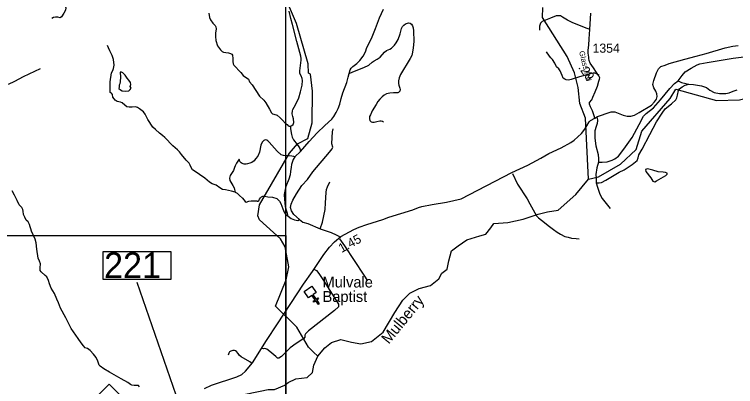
# Model space of a CAD drawing. Extents: x 1159738 to 1321356, y 736314 to 882035.
# Drawn here: x 1209848 to 1219753, y 803906 to 809013 of the extents above; entities that cross this region are included whole.
import ezdxf

# ---------------------------------------------------------------- set-up
doc = ezdxf.new("R2010")
doc.units = 0
for name, color, linetype in [('Exist Cultural Church CELL', 7, 'Continuous'), ('Exist Cultural Church Label', 7, 'Continuous'), ('Exist Hydrographic Creek Single Shore', 7, 'Continuous'), ('Exist Hydrographic Creek Single Shore Label', 7, 'Continuous'), ('Exist Hydrographic Pond Under 1500 Sq Ft', 7, 'Continuous'), ('Exist Road Non-System Type 51', 7, 'Continuous'), ('Exist Road Primary NC Attributed', 7, 'Continuous'), ('Exist Road Primary NC Mileage Hundredths English Label', 7, 'Continuous'), ('Exist Road Primary NC Shield CELL', 7, 'Continuous'), ('Exist Road Secondary Mileage Hundredths English Label', 7, 'Continuous'), ('Exist Road Secondary Structure Standard Bridge Number Label', 7, 'Continuous'), ('Exist Road Secondary Type 51 Attributed', 7, 'Continuous'), ('Exist Road Secondary Type 51 Label', 7, 'Continuous'), ('Exist Road Secondary Type 51 Number Label', 7, 'Continuous'), ('Map Preparation Inset Cut Line', 7, 'Continuous')]:
    doc.layers.add(name, color=color, linetype=linetype)

msp = doc.modelspace()

# ---------------------------------------------------------------- linework, layer by layer
at = {"layer": 'Exist Cultural Church CELL'}
msp.add_lwpolyline([(1213993.7, 805198.8), (1213947.4, 805165.7), (1213991.5, 805103.7), (1214017.6, 805122.2), (1214026.8, 805109.2), (1214000.8, 805090.7), (1214035.6, 805041.7), (1214022.6, 805032.4), (1213987.7, 805081.4), (1213961.6, 805062.8), (1213952.4, 805075.9), (1213978.4, 805094.4), (1213934.3, 805156.4), (1213887.3, 805123.1), (1213825.5, 805209.8), (1213932, 805285.6)], close=True, dxfattribs=at)
at = {"layer": 'Exist Hydrographic Creek Single Shore'}
for points in [[(1214013.3, 804322.9), (1213956.3, 804378.4), (1213886.3, 804446.5), (1213727.3, 804718.8), (1213435.3, 805010.2), (1213578.3, 805371.7), (1213616.3, 805548.2), (1213565.3, 805825), (1213501.3, 805934.6), (1213216.3, 806193.1), (1213193.3, 806249.3), (1213214.2, 806399.9), (1213625.3, 807107.3), (1213737.2, 807236.4), (1213880.2, 807309), (1213936.2, 807524.5), (1213940.2, 807957.8), (1213913.3, 808191.3), (1213888.2, 808208.3), (1213883.2, 808333.1), (1213723.2, 808887.8), (1213597.2, 809175.9)], [(1217735.3, 806752.5), (1217690.3, 807587.2), (1217613.3, 807788.9), (1217593.3, 808009.3), (1217541.2, 808210.5), (1217438.3, 808435.9), (1217103.2, 808971.1), (1217106.8, 809110.1)], [(1217735.3, 806752.5), (1217869.3, 806782.7), (1218174.3, 806957.1), (1218388.3, 807159.6), (1218467.2, 807409.5), (1218856.6, 807857.7), (1218930.6, 807986.3), (1219490.3, 807830.1), (1219807.3, 807840.2), (1220345.3, 807973.8)], [(1214013.3, 804322.9), (1214112, 804437.9), (1214204.7, 804510.6), (1214329.7, 804551), (1214479, 804514.6), (1214608, 804490.4), (1214753.2, 804522.7), (1214910.5, 804651.8), (1215071.8, 804922.3), (1215180.7, 805091.8), (1215277.5, 805188.6), (1215406.6, 805253.2), (1215563.9, 805293.6), (1215676.8, 805382.3), (1215717.1, 805463.1), (1215789.7, 805515.5), (1215813.9, 805632.6), (1215850.2, 805769.8), (1215943, 805838.4), (1216064, 805919.1), (1216241.4, 805975.6), (1216321.1, 805997.8), (1216393.7, 806082.6), (1216434, 806143.1), (1216623.6, 806155.2), (1216837.3, 806203.7), (1217043, 806272.3), (1217172.1, 806304.6), (1217317.3, 806324.7), (1217559.3, 806542.7), (1217735.3, 806752.5)], [(1212212.4, 803125.7), (1212271, 803160.6), (1212404, 803221.1), (1212525, 803285.7), (1212585.5, 803342.2), (1212623.3, 803452.6), (1212601.7, 803535.9), (1212601.7, 803576.3), (1212654.1, 803661), (1212738.8, 803725.6), (1212976.8, 803790.2), (1213222.8, 803842.6), (1213331.7, 803866.9), (1213420.4, 803866.9), (1213561.6, 803923.4), (1213605.9, 803959.7), (1213714.8, 804012.2), (1213868.1, 804032.3), (1213940.7, 804100.9), (1213960.8, 804197.8), (1214013.3, 804322.9)]]:
    msp.add_lwpolyline(points, dxfattribs=at)
at = {"layer": 'Exist Hydrographic Pond Under 1500 Sq Ft'}
for points in [[(1211301.1, 808219.1), (1211305.5, 808151.9), (1211301.1, 808094.6), (1211294.5, 808059.3), (1211287.9, 808043.9), (1211284.6, 808018.6), (1211283.5, 807997.6), (1211305.5, 807977.8), (1211326.4, 807962.4), (1211378.1, 807958), (1211417.8, 807962.4), (1211438.7, 807982.2), (1211450.8, 807999.8), (1211439.8, 808023), (1211446.4, 808052.7), (1211440.9, 808080.3), (1211418.9, 808108.9), (1211395.8, 808138.7), (1211368.2, 808178.3), (1211337.4, 808210.3), (1211319.8, 808222.4)], [(1218517.9, 806884.6), (1218521.4, 806859.1), (1218587.4, 806772.1), (1218618.7, 806724.6), (1218641.9, 806717.6), (1218668.5, 806731.5), (1218793.7, 806801.1), (1218812.2, 806822), (1218814.5, 806834.8), (1218791.4, 806845.2), (1218757.8, 806846.3), (1218689.4, 806854.5), (1218615.2, 806874.2), (1218560.8, 806888.1), (1218541.1, 806892.7), (1218529.5, 806891.6)]]:
    msp.add_lwpolyline(points, close=True, dxfattribs=at)
at = {"layer": 'Exist Road Non-System Type 51'}
msp.add_line((1213777.1, 807132.2), (1213698.1, 807059), dxfattribs=at)
for points in [[(1210456.7, 809178.8), (1210516.3, 809145.9), (1210538.9, 809129.4), (1210549.2, 809116), (1210552.3, 809101.6), (1210548.2, 809072.8), (1210526.6, 809029.6), (1210496.8, 808982.2), (1210478.3, 808967.8), (1210444.3, 808974), (1210411.4, 808974), (1210384.7, 808969.9), (1210361, 808956.5)], [(1213638.4, 807481.5), (1213657.9, 807488.7), (1213678.5, 807504.2), (1213686.7, 807528.9), (1213682.6, 807578.3), (1213671.3, 807613.3), (1213662.1, 807647.2), (1213666.2, 807688.4), (1213671.3, 807706.9), (1213688.8, 807739.9), (1213726.8, 807807.8), (1213752.2, 807869.7), (1213775.9, 807952.1), (1213798.5, 808041.6), (1213804.6, 808104.4), (1213799.5, 808135.3), (1213785.1, 808168.2), (1213769.7, 808202.1), (1213767.6, 808240.2), (1213776.9, 808311.2), (1213786.1, 808385.3), (1213788.2, 808408.4), (1213783.1, 808441.3), (1213726.5, 808643), (1213669, 808875.1), (1213644.4, 808957.9), (1213622.8, 809055.7)], [(1214445.8, 808201.7), (1214458.1, 808252.1), (1214471.5, 808274.8), (1214498.2, 808300.5), (1214551.7, 808340.6), (1214591.8, 808379.7), (1214638.1, 808441.5), (1214672, 808501.2), (1214690.5, 808557.8), (1214752, 808681.4), (1214808.6, 808818.3), (1214864.1, 808965.5), (1214918.6, 809083.8)], [(1212517.2, 809029.1), (1212529.5, 808970.5), (1212541.9, 808937.5), (1212572.7, 808895.3), (1212603.6, 808863.4), (1212612.8, 808842.3), (1212616.9, 808813.5), (1212611.8, 808753.8), (1212609.7, 808710.6), (1212613.8, 808654), (1212639.5, 808579.9), (1212678.6, 808525.3), (1212701.2, 808503.7), (1212721.8, 808493.4), (1212753.7, 808489.3), (1212790.7, 808486.2), (1212816.2, 808478.6), (1212832.6, 808467.3), (1212842.9, 808455), (1212849.1, 808408.6), (1212847, 808367.5), (1212852.2, 808336.6), (1212860.4, 808316), (1212956, 808217.2), (1212990, 808175), (1213062, 808125.6), (1213078.4, 808089.6), (1213115.4, 808048.4), (1213215.9, 807889.6), (1213272.5, 807837.2), (1213299.2, 807799.1), (1213349.6, 807711.6), (1213378.4, 807664.3), (1213392.6, 807650.3), (1213409.1, 807644.1), (1213457.4, 807628.7), (1213499.6, 807591.7), (1213531.4, 807561.8), (1213573.6, 807515.5), (1213592.1, 807502.1), (1213608.6, 807485.7), (1213621.9, 807481.5), (1213638.4, 807481.5)], [(1217757.8, 808805.5), (1217716.5, 808822.1), (1217610.4, 808860.7), (1217508.5, 808902), (1217445.1, 808932.3), (1217374.9, 808977.8), (1217348.7, 808993), (1217321.1, 808995.7), (1217286.7, 808991.6), (1217210.9, 808959.9), (1217098, 808914.4), (1217075.9, 808891), (1217060.8, 808852.4), (1217062.2, 808827.6), (1217060.8, 808795.9)], [(1214445.8, 808201.7), (1214496.6, 808223.2), (1214645.8, 808283.9), (1214714.1, 808315.7), (1214762.3, 808356.2), (1214786.9, 808377.1), (1214828.3, 808400.2), (1214870.7, 808426.2), (1214933.3, 808494.6), (1214960.2, 808517.7), (1215006.4, 808538), (1215029.5, 808549.5), (1215068, 808592.9), (1215090.2, 808621.8), (1215118, 808670.4), (1215144.9, 808746.6), (1215164.2, 808818.8), (1215179.6, 808848.7), (1215195, 808867), (1215220, 808886.3), (1215262.4, 808896.9), (1215284.3, 808893.9), (1215301.6, 808881.4), (1215317, 808858.2), (1215326.7, 808828.4), (1215331.5, 808787), (1215332.4, 808642.4), (1215323.8, 808555.7), (1215316.1, 808494.1), (1215304.5, 808447.8), (1215283.3, 808408.3), (1215149.7, 808190.2), (1215131.4, 808144), (1215122.7, 808102.6), (1215122.7, 808066), (1215128.5, 808042.8), (1215141, 808000.9), (1215146.8, 807983.6), (1215141, 807961.4), (1215133.3, 807948.9), (1215123.7, 807943.1), (1215114.1, 807938.3), (1215054.4, 807935.4), (1215005.3, 807932.5), (1214957.1, 807921.9), (1214925.4, 807906.5), (1214901.3, 807883.4), (1214868.6, 807848.7), (1214840.6, 807818.8), (1214815.6, 807778.4), (1214761.9, 807692.2), (1214751.3, 807668.1), (1214738.8, 807636.3), (1214727.3, 807611.3), (1214725.4, 807580.4), (1214730.2, 807555.4), (1214746.5, 807539), (1214766.8, 807533.2), (1214787.9, 807534.2), (1214826.4, 807542.9), (1214866.9, 807552.5), (1214884.2, 807553.4), (1214902.5, 807548.6), (1214916.8, 807539.6)], [(1212878.6, 806572.1), (1212829.1, 806586.5), (1212748.7, 806605.2), (1212704.7, 806611.8), (1212667.2, 806631.6), (1212619.9, 806668), (1212565.9, 806687.8), (1212526.3, 806711), (1212461.3, 806764.9), (1212392, 806815.6), (1212315.4, 806865.9), (1212293.3, 806882.4), (1212275.7, 806913.3), (1212263.6, 806944.1), (1212249.3, 806973.9), (1212206.4, 807012.4), (1212141.4, 807089.5), (1212115, 807127), (1212088.5, 807156.8), (1212025.8, 807209.6), (1211913.7, 807322.5), (1211881.8, 807351.2), (1211839.9, 807385.3), (1211783.8, 807431.6), (1211750.7, 807468), (1211680.3, 807571.5), (1211657.5, 807617.3), (1211645.4, 807644.8), (1211618.9, 807676.8), (1211567.2, 807716.2), (1211539.7, 807737.2), (1211513.3, 807743.8), (1211467, 807741.6), (1211425.2, 807738.3), (1211394.3, 807746), (1211362.4, 807769.1), (1211326.1, 807797.8), (1211304.1, 807807.7), (1211257.8, 807819.8), (1211232.5, 807835.2), (1211216, 807852.9), (1211198.4, 807877.1), (1211194, 807914.6), (1211179.6, 807933.3), (1211161.7, 807942.7), (1211162.8, 807968.1), (1211163.9, 808088.2), (1211180.4, 808209.4), (1211199.1, 808243.5), (1211209, 808270), (1211217.8, 808315.1), (1211209.9, 808392.7), (1211191.1, 808448.9), (1211160.3, 808515), (1211139.6, 808555.3), (1211127.5, 808585)], [(1217879, 808180.4), (1217843.2, 808198.3), (1217819.8, 808205.2), (1217797.7, 808208), (1217771.6, 808203.8), (1217593.9, 808152.8), (1217494.7, 808119.7), (1217457.5, 808108.7), (1217427.2, 808114.2), (1217407.9, 808123.9), (1217384.5, 808137.7), (1217369.3, 808174.9), (1217344.6, 808241), (1217323.9, 808268.6), (1217295, 808293.4), (1217271.5, 808345.8), (1217239.9, 808395.4), (1217216.4, 808417.5), (1217195.8, 808438.2), (1217157.2, 808498.8)], [(1218963.8, 808102.9), (1219017.5, 808176), (1219058.8, 808224.2), (1219141.5, 808276.6), (1219224.1, 808319.3), (1219264.1, 808335.9), (1219361.9, 808355.2), (1219720.8, 808412.7), (1219970.2, 808445.8), (1220177.7, 808462.2), (1220227.3, 808463.6), (1220250.2, 808460.9)], [(1209768.8, 808055.7), (1209854.1, 808095.8), (1209972.4, 808160.2), (1210205.1, 808271.5)], [(1213777.1, 807132.2), (1213894.5, 807268), (1214006.2, 807387.5), (1214113.1, 807486.7), (1214208.9, 807576.6), (1214234.9, 807611.3), (1214267.6, 807666.2), (1214294.6, 807724), (1214318.6, 807779.9), (1214335, 807859.9), (1214360, 807936.9), (1214411.8, 808079.7), (1214431.1, 808151), (1214445.8, 808201.7)], [(1217869.1, 806984.9), (1217921.7, 806986.7), (1217989.2, 806992.2), (1218056.7, 807011.5), (1218095.2, 807030.8), (1218144.8, 807068), (1218220.6, 807163.1), (1218330.8, 807325.8), (1218427.2, 807503.6), (1218490.3, 807618.6), (1218523.3, 807651.6), (1218625.3, 807733), (1218723.1, 807840.5), (1218848.4, 807994.9), (1218914.2, 808064.3), (1218963.8, 808102.9)], [(1218963.8, 808102.9), (1219010.6, 808079.5), (1219068.4, 808065.7), (1219110.8, 808055.3)], [(1217836.1, 806703), (1217878.6, 806700.5), (1217913, 806704.7), (1217969.5, 806736.4), (1218154.1, 806846.6), (1218221.6, 806878.3), (1218334.5, 806951.4), (1218399.3, 807009.3), (1218415.8, 807045.1), (1218425.4, 807087.9), (1218468.1, 807163.7), (1218573.9, 807365.3), (1218668.9, 807540.4), (1218746.1, 807656.2), (1218786, 807716.8), (1218871.4, 807787.1), (1218930.4, 807841.7), (1218944.1, 807867.8), (1218953.8, 807905.1), (1218967.6, 807968.5), (1218981.3, 807991.9), (1219019.9, 808019.5), (1219061.2, 808042.9), (1219110.8, 808055.3), (1219176.9, 808049.8), (1219287.1, 808033.3), (1219351.9, 808011.2), (1219401.5, 807975.4), (1219460, 807943.7), (1219531.7, 807928.5), (1219621.2, 807925.8), (1219665.3, 807935.4), (1219720.4, 807958.9), (1219774.1, 807978.2)], [(1217849.8, 807594.2), (1217858.1, 807557), (1217852.6, 807517), (1217840.2, 807472.9), (1217822.3, 807416.4), (1217818.2, 807366.8), (1217818.2, 807314.4), (1217834.7, 807211), (1217865, 807089.7), (1217871.9, 807029), (1217869.1, 806984.9)], [(1213638.4, 807481.5), (1213639.4, 807444.3), (1213653.8, 807366.3), (1213662.5, 807328.7), (1213680.8, 807293.1), (1213733.7, 807227.6), (1213754, 807195.8), (1213768.4, 807172.7), (1213773.2, 807150.5), (1213777.1, 807132.2)], [(1213762.6, 806199.4), (1213683.8, 806265.8), (1213655.1, 806316), (1213640.7, 806362.7), (1213649.7, 806407.5), (1213673, 806464.9), (1213723.2, 806549.2), (1213794.9, 806665.8), (1213873.8, 806746.6), (1213947.3, 806852.4), (1214174.4, 807122.5), (1214213.8, 807167.3), (1214221, 807190.7), (1214208.4, 807239.1), (1214210.2, 807323.4), (1214215.6, 807402.3), (1214224.6, 807441.8)], [(1213698.1, 807059), (1213683.9, 807063.8), (1213658.6, 807069.3), (1213621.2, 807071.5), (1213589.2, 807071.5), (1213545.2, 807074.8), (1213513.3, 807088), (1213457.1, 807138.7), (1213345.9, 807258.8), (1213329.4, 807278.6), (1213314, 807286.4), (1213289.8, 807290.8), (1213272.1, 807284.2), (1213249, 807262.1), (1213233.6, 807216.9), (1213216, 807124.4), (1213189.6, 807068.2), (1213159.8, 807030.7), (1213138.9, 807004.3), (1213108.1, 806982.3), (1213082.8, 806970.1), (1213050.8, 806962.4), (1213028.8, 806958), (1213004.6, 806956.9), (1212974.9, 806967.9), (1212960.6, 806977.9), (1212946.2, 806996.6), (1212936.3, 807026.3)], [(1212936.3, 807026.3), (1212898.4, 806972.7), (1212880.8, 806936.3), (1212868.7, 806911), (1212855.5, 806869.1), (1212812.6, 806804.1), (1212802.6, 806764.5), (1212808.2, 806735.8), (1212850, 806666.4), (1212864.3, 806632.7), (1212870.9, 806611.8), (1212878.6, 806572.1)], [(1213698.1, 807059), (1213678, 807020.8), (1213654.7, 806954.4), (1213647.6, 806918.5), (1213642.2, 806855.7), (1213635, 806810.9), (1213618.9, 806753.5), (1213577.6, 806651.2), (1213565.1, 806608.2), (1213552.5, 806541.8), (1213556.1, 806473.6), (1213561.5, 806425.2), (1213565.1, 806376.8), (1213581.2, 806326.5), (1213593.8, 806283.5), (1213600.9, 806253), (1213606.3, 806245.8)], [(1217869.1, 806984.9), (1217847.1, 806909.8), (1217833.3, 806816.1), (1217836.1, 806765.1), (1217836.1, 806703)], [(1216687, 806830.4), (1216760, 806685.5), (1216889.8, 806480.2), (1216929.1, 806415.9), (1217020.6, 806251.2), (1217045, 806221.1), (1217085.5, 806187.4), (1217196.8, 806103.9), (1217253.1, 806060.5), (1217301.8, 806023.4), (1217350.4, 805996.8), (1217408.4, 805966.6), (1217452.4, 805955), (1217499.9, 805944.6), (1217563.6, 805939.9), (1217603, 805933)], [(1214045.9, 806072.1), (1214077.5, 806162.3), (1214117, 806334.5), (1214122.3, 806427.8), (1214127.7, 806571.3), (1214134.9, 806612.6), (1214149.2, 806646.6), (1214179.7, 806716.6)], [(1217836.1, 806703), (1217856.8, 806641), (1217888.4, 806545.9), (1217918.6, 806486.1), (1218032.9, 806349.6)], [(1209989, 806230), (1209973.9, 806265.8), (1209970.4, 806311.1), (1209961.7, 806337.2), (1209947.8, 806363.3), (1209930.4, 806382.5), (1209914.7, 806401.7), (1209886.9, 806459.1), (1209848.6, 806534), (1209817.2, 806589.8)], [(1212878.6, 806572.1), (1212909.3, 806558.2), (1212939.8, 806527.7), (1212981, 806490), (1213016.9, 806443.4), (1213033, 806434.4), (1213067.1, 806448.8), (1213097.6, 806454.2), (1213137, 806456), (1213176.4, 806456), (1213183.6, 806452.4), (1213196.2, 806450.6), (1213205.1, 806456), (1213215.9, 806477.5), (1213226.6, 806497.2), (1213242.8, 806509.8), (1213258.9, 806518.7), (1213287.6, 806518.7), (1213327, 806511.6), (1213391.6, 806504.4), (1213452.5, 806486.4), (1213490.2, 806450.6), (1213508.1, 806420.1), (1213535, 806342.9), (1213551.1, 806299.9), (1213570.8, 806271.2), (1213592.3, 806255), (1213606.3, 806245.8)], [(1211567.8, 803902.3), (1211552.1, 803919.4), (1211535, 803922.3), (1211513.6, 803922.3), (1211490.7, 803922.3), (1211460.7, 803923.7), (1211442.1, 803932.3), (1211403.5, 803960.9), (1211315, 804010.9), (1211249.2, 804048.1), (1211154.9, 804105.3), (1211076.3, 804151), (1211026.3, 804183.9), (1211013.5, 804201.1), (1210993.5, 804255.4), (1210972, 804305.5), (1210933.5, 804349.8), (1210886.3, 804402.7), (1210852, 804427), (1210820.6, 804437), (1210796.3, 804467), (1210766.3, 804504.2), (1210724.9, 804564.3), (1210626.3, 804704.4), (1210589.1, 804775.9), (1210553.4, 804850.2), (1210479.1, 804981.8), (1210452, 805053.2), (1210430.5, 805106.1), (1210397.7, 805183.4), (1210354.8, 805254.8), (1210329.1, 805313.5), (1210317.7, 805363.5), (1210293.4, 805410.7), (1210269.1, 805430.7), (1210217.6, 805479.3), (1210203.4, 805500.8), (1210200.5, 805536.5), (1210204.8, 805588), (1210191.9, 805628), (1210171.9, 805668.1), (1210157.6, 805789.6), (1210147.6, 805879.7), (1210134.8, 805929.7), (1210084.8, 806039.8), (1210071.9, 806068.4), (1210063.3, 806097), (1210056.2, 806128.5), (1210036.2, 806167.1), (1210009, 806189.9), (1209989, 806230)], [(1213606.3, 806245.8), (1213647.9, 806212), (1213692.7, 806192.2), (1213741.1, 806186.9), (1213762.6, 806199.4)], [(1213762.6, 806199.4), (1213809.3, 806161.7), (1213877.4, 806142), (1214045.9, 806072.1)], [(1214045.9, 806072.1), (1214199.4, 806018.8), (1214269.3, 805988.3), (1214305.2, 805970.3), (1214328.5, 805948.8)], [(1214313.9, 805933.6), (1214380.2, 805836.7), (1214645.5, 805434.9), (1214697.5, 805355.9)], [(1213968, 805511.1), (1213994.9, 805500.4), (1214030.8, 805455.5), (1214095.3, 805360.4), (1214211.8, 805175.7), (1214297.9, 805035.7), (1214301.5, 805014.2), (1214297.9, 804998.1), (1214242.3, 804951.4), (1213887.4, 804669.8), (1213844.4, 804631), (1213839.1, 804609.5), (1213837.3, 804582.5), (1213824.7, 804564.6), (1213718.9, 804496.4), (1213636.5, 804435.4), (1213564.8, 804370.9), (1213516.4, 804318.8), (1213480.5, 804293.7), (1213463.4, 804295.7), (1213436.5, 804319.1), (1213355.8, 804385.4), (1213314.6, 804417.7), (1213289.5, 804426.7), (1213269.8, 804424.9), (1213257.2, 804426.7)], [(1213114.8, 804223.2), (1213080.1, 804246.3), (1212960.7, 804314.8), (1212932.9, 804336.8), (1212920.2, 804360), (1212899.3, 804387.8), (1212886.5, 804398.3), (1212871.5, 804401.7), (1212849.5, 804401.7), (1212819.3, 804391.3), (1212803.1, 804380.9), (1212795, 804364.6), (1212785.7, 804336.8)]]:
    msp.add_lwpolyline(points, dxfattribs=at)
at = {"layer": 'Exist Road Primary NC Attributed'}
for points in [[(1217818.4, 807589.6), (1217857.8, 807610.7), (1217913.5, 807628.5), (1217977, 807651.9), (1218043.9, 807674.2), (1218092.9, 807677.6), (1218141.9, 807657.5), (1218209.9, 807630.7), (1218265.6, 807615.1), (1218315.7, 807615.1), (1218364.8, 807630.7), (1218427.2, 807666.4), (1218597.1, 807768.8), (1218641.6, 807812.3), (1218668.4, 807850.2), (1218676.2, 807888.1), (1218672.8, 807923.8), (1218659.5, 807960.6), (1218628.3, 808006.3), (1218617.1, 808050.9), (1218628.3, 808104.4), (1218668.3, 808210.9), (1218693.9, 808265.5), (1218727.4, 808300.1), (1218787.5, 808319), (1218838.8, 808338), (1219056.7, 808401.2), (1219213.8, 808442.5), (1219347.6, 808477), (1219608.9, 808553.6), (1219717, 808579.2), (1219788.4, 808584.8)], [(1212458, 803878.3), (1212556.1, 803926.5), (1212904, 804040.7), (1212970, 804069.3), (1213023.5, 804115.7), (1213117.5, 804232.5), (1213308.4, 804536), (1213461.8, 804764.6), (1213819.8, 805309.5), (1213942.9, 805484.4), (1214097.6, 805719), (1214176.1, 805817.2), (1214245.7, 805892.2), (1214331.3, 805963.6), (1214510.4, 806062), (1214585.2, 806093.7), (1214686.2, 806130.3), (1214910.2, 806199.3), (1214991.1, 806232.8), (1215318.1, 806333.4), (1215397.5, 806364.3), (1215442, 806375.5), (1215584.3, 806405.8), (1215784.9, 806434.8), (1215984.3, 806481.4), (1216678.5, 806845.1), (1216898.8, 806944.8), (1217078.4, 807039.9), (1217189.5, 807104.1), (1217358.9, 807180.3), (1217492.3, 807255.5), (1217535, 807287.5), (1217636.4, 807377.5), (1217683.7, 807440.4), (1217708.6, 807481.9), (1217743.5, 807539.4), (1217759.9, 807557.1), (1217818.4, 807589.6)]]:
    msp.add_lwpolyline(points, dxfattribs=at)
at = {"layer": 'Exist Road Primary NC Shield CELL'}
msp.add_lwpolyline([(1210816.4, 803606.5), (1211149.4, 803939.5), (1211482.4, 803606.5), (1211149.4, 803273.5)], close=True, dxfattribs=at)
at = {"layer": 'Exist Road Secondary Structure Standard Bridge Number Label'}
msp.add_line((1212262.2, 803239), (1211531.7, 805331.9), dxfattribs=at)
msp.add_lwpolyline([(1211067.2, 805760.9), (1211996.2, 805760.9), (1211996.2, 805376.8), (1211067.2, 805376.8)], close=True, dxfattribs=at)
at = {"layer": 'Exist Road Secondary Type 51 Attributed'}
msp.add_lwpolyline([(1217818.4, 807589.6), (1217812.8, 807619.3), (1217788.1, 807689.4), (1217774.4, 807716.5), (1217760, 807745.1), (1217747.8, 807780.4), (1217747.8, 807804), (1217778.2, 807842.3), (1217793.4, 807877.6), (1217823.7, 807949.8), (1217857.1, 808030.7), (1217875.3, 808098.5), (1217884.4, 808123.5), (1217887.5, 808144.1), (1217875.3, 808169.1), (1217842.7, 808218.4), (1217801.1, 808279.3), (1217756.4, 808344.2), (1217743.1, 808380.5), (1217735.7, 808407), (1217736, 808425.1), (1217729.6, 808481.2), (1217729.6, 808523.9), (1217735.7, 808591.7), (1217741, 808679.2), (1217750.1, 808807.3), (1217766.1, 809030.4)], dxfattribs=at)
at = {"layer": 'Map Preparation Inset Cut Line'}
for points in [[(1213574.8, 811005.5), (1289258, 811005.5), (1289258, 782300.2), (1274049.2, 782296.9), (1274049.2, 766757), (1213574.8, 766757)], [(1213574.8, 778108.9), (1194107.7, 778108.9), (1194107.7, 805981), (1213574.8, 805981)]]:
    msp.add_lwpolyline(points, close=True, dxfattribs=at)

# ---------------------------------------------------------------- texts
at = {"layer": 'Exist Cultural Church Label'}
for s, p in [('Mulvale', (1214080.2, 805265.6)), ('Baptist', (1214080.2, 805066.4))]:
    msp.add_text(s, height=150, dxfattribs=at).set_placement(p)
at = {"layer": 'Exist Hydrographic Creek Single Shore Label'}
msp.add_text('Mulberry', height=150, rotation=50.70384, dxfattribs=at).set_placement((1214990.1, 804479.6))
at = {"layer": 'Exist Road Primary NC Mileage Hundredths English Label'}
msp.add_text('1.45', height=125, rotation=28.79541, dxfattribs=at).set_placement((1214340.9, 805737.4))
at = {"layer": 'Exist Road Secondary Mileage Hundredths English Label'}
msp.add_text('.29', height=125, rotation=304.55711, dxfattribs=at).set_placement((1217588.7, 808283.1))
at = {"layer": 'Exist Road Secondary Structure Standard Bridge Number Label'}
msp.add_text('221', height=350, dxfattribs=at).set_placement((1211079.7, 805396.5))
at = {"layer": 'Exist Road Secondary Type 51 Label'}
msp.add_text('Glass Rd', height=75, rotation=283.60119, dxfattribs=at).set_placement((1217603, 808504.1))
at = {"layer": 'Exist Road Secondary Type 51 Number Label'}
msp.add_text('1354', height=125, dxfattribs=at).set_placement((1217790.1, 808487.7))

doc.saveas('drawing.dxf')
